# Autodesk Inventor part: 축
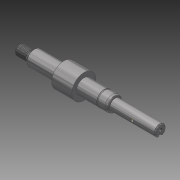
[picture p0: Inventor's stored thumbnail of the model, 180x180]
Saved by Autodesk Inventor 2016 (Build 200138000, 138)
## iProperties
Created: 2016-08
Part Number: 축
Material: 강철, 탄소
Document SubType Name: Modeling
Designer: mduedu
Density: 7.87 g/cm^3
Appearance: 반광택
Author: mduedu
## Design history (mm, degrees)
sketch "스케치1"
  geometry: L1 (-72.5, 0)-(72.5, 0); L2 (-72.5, 0)-(-72.5, 5); L3 (-72.5, 5)-(-58.5, 5); L4 (-58.5, 5)-(-58.5, 7.5); L5 (-58.5, 7.5)-(25.855, 7.5); L6 (27.5, 6.55)-(27.5, 5.5); L7 (27.5, 5.5)-(72.5, 5.5); L8 (72.5, 5.5)-(72.5, 0); L9 (27.5, 6.55)-(25.855, 7.5); 2 further points
  constraints: 18 end point, 5 parallel, 2 perpendicular, 1 coincident, 1 horizontal, 1 midpoint
  dimensions: "d0" = 145 distance of L1.start L1.end; "d2" = 14 distance of L2.end L3.end; "d4" = 10 diameter of L3 L1; "d5" = 15 diameter of L5 L1; "d6" = 11 diameter of L7 L1; "d63" = 45 distance between parallel lines of L6 L8; "d64" = 30 deg angle of L5 L9; "d65" = 13.1 diameter of L6.start L1
revolve "회전1" sketch "스케치1" stored, may be unused: angle "d7" = 90 deg
sketch "스케치2"
  geometry: L1 (-58.5, -5)-(-58.5, 5) reference; L2 (72.5, -5.5)-(72.5, 5.5) reference; L3 (-58.5, 0)-(72.5, 0); L4 (-60.5, 4.5)-(-60.5, 5); L5 (-60.5, 5)-(-58.5, 5); L6 (-58.5, 5)-(-58.5, 4.5); L7 (-60.5, 4.5)-(-58.5, 4.5); 1 further point
  constraints: 10 end point, 2 midpoint, 1 parallel, 1 perpendicular, 1 point on line
  dimensions: "d8" = 2 distance of L4.end L5.end; "d10" = 10 diameter of L5 L3; "d11" = 9 diameter of L7 L3
revolve "회전2" sketch "스케치2" stored, may be unused: angle "d12" = 90 deg
node "작업 평면1"
sketch "스케치3"
  geometry: C1 r 12 at (0, 0); 1 further point
  constraints: 1 centre point, 1 coincident
  dimensions: "d15" = 24 diameter of C1
extrude "돌출1" join sketch "스케치3" distance "d16" = 20; taper "d17" = 0 deg
sketch "스케치5"
  geometry: L1 (-72.5, -5)-(-72.5, 5) reference; L2 (72.5, -5.5)-(72.5, 5.5) reference; L3 (-72.5, 0)-(72.5, 0); L4 (-8.5, 7.5)-(25.855, 7.5) reference; L5 (12.65, 7.5)-(11.5, 7.5); L6 (11.5, 7.5)-(11.5, 7.15); L7 (11.5, 7.15)-(12.65, 7.15); L8 (12.65, 7.15)-(12.65, 7.5); L9 (-8.5, -12)-(-8.5, 12) reference; 1 further point
  constraints: 10 end point, 2 midpoint, 2 parallel, 1 horizontal, 1 perpendicular, 1 point on line
  dimensions: "d20" = 1.15 distance between parallel lines of L8 L6; "d21" = 14.3 diameter of L7 L3; "d82" = 20 distance between parallel lines of L9 L6
revolve "회전3" sketch "스케치5" stored, may be unused: angle "d22" = 90 deg
node "작업 평면3"
sketch "스케치6"
  geometry: L1 (-6.5, 2)-(-22.5, 2); L2 (-22.5, 2)-(-22.5, -2); L3 (-22.5, -2)-(-6.5, -2); L4 (-22.5, 5.5)-(-22.5, -5.5) reference; A1 r 2 centre (-6.5, 0) between (-6.5, -2) and (-6.5, 2); 2 further points
  constraints: 6 end point, 2 midpoint, 2 point on circle, 2 tangent, 1 centre point, 1 horizontal, 1 horizontal alignment, 1 parallel, 1 perpendicular
  dimensions: "d23" = 4 distance between parallel lines of L3 L1; "d62" = 18 dimension on A1 L2
extrude "돌출2" cut sketch "스케치6" distance "d25" = 2.5; taper "d26" = 0 deg
feature "스레드1" dims "d27" = 10, "d28" = 0
chamfer "모따기5" distance "d41" = 0.5; stored, may be unused: second distance "d42" = 2, angle "d43" = 45 deg
chamfer "모따기7" distance "d47" = 1; stored, may be unused: second distance "d48" = 2, angle "d49" = 45 deg
chamfer "모따기8" distance "d50" = 1; stored, may be unused: second distance "d51" = 2, angle "d52" = 45 deg
sketch "스케치8"
  geometry: 1 further point
hole "구멍1" sketch "스케치8" at (2, 3.5) diameter "d53" = 3.242; stored, may be unused: countersink angle "d57" = 90 deg, drill point angle "d59" = 120 deg; dims "d54" = 10, "d55" = 4, "d56" = 2, "d58" = 12
fillet "모깎기1" dims "d66" = 4, "d67" = 0.5
sketch "스케치10"
  geometry: L1 (-27.5, 5.5)-(-71.5, 5.5) reference; L2 (-51, 5.5)-(-49.5, 4); L3 (-49.5, 4)-(-49.5, 5.5); L4 (-72.5, -4.5)-(-72.5, 4.5) reference; 3 further points
  constraints: 4 end point, 1 midpoint, 1 perpendicular, 1 point on line
  dimensions: "d77" = 45 deg angle of L2 L3; "d78" = 3 diameter of L2.start L3; "d80" = 23 distance between parallel lines of L4 L3
revolve "회전4" sketch "스케치10" stored, may be unused: angle "d81" = 90 deg
node "작업점1"
node "솔리드1"
other parameters: "d13" = -44
